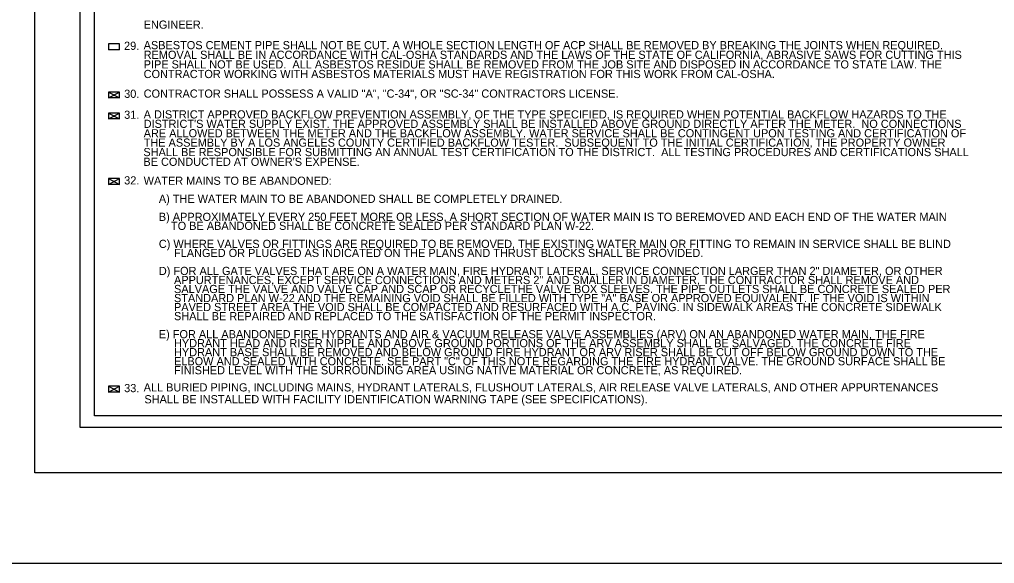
# Model space of a CAD drawing. Extents: x 837 to 1117, y 1316 to 1424.
# Drawn here: x 842.85 to 853.59, y 1398.24 to 1404.23 of the extents above; entities that cross this region are included whole.
import ezdxf

# ---------------------------------------------------------------- set-up
doc = ezdxf.new("R2010")
doc.units = 0
for name, color, linetype in [('0 (Construction)', 7, 'Continuous'), ('BASEMAP', 7, 'Continuous'), ('LLINES', 7, 'Continuous'), ('TEXT', 7, 'Continuous')]:
    doc.layers.add(name, color=color, linetype=linetype)

msp = doc.modelspace()

# ---------------------------------------------------------------- linework, layer by layer
at = {"layer": '0 (Construction)'}
msp.add_lwpolyline([(841.77, 1422.24), (877.77, 1422.24), (877.77, 1398.24), (841.77, 1398.24)], close=True, dxfattribs=at)
at = {"layer": 'BASEMAP'}
for p, q in [((843.02, 1399.24), (843.02, 1421.24)), ((843.52, 1399.74), (843.52, 1420.74)), ((843.678, 1399.867), (843.678, 1420.065)), ((854.857, 1399.867), (843.678, 1399.867)), ((876.52, 1399.74), (843.52, 1399.74)), ((877.02, 1399.24), (843.02, 1399.24))]:
    msp.add_line(p, q, dxfattribs=at)
at = {"layer": 'LLINES'}
for p, q in [((843.95, 1403.965), (843.83, 1403.965)), ((843.83, 1403.965), (843.83, 1403.9)), ((843.95, 1403.9), (843.95, 1403.965)), ((843.95, 1403.9), (843.83, 1403.9)), ((843.831, 1403.435), (843.95, 1403.371)), ((843.831, 1403.371), (843.95, 1403.435)), ((843.95, 1403.435), (843.831, 1403.435)), ((843.95, 1403.371), (843.95, 1403.435)), ((843.95, 1403.371), (843.831, 1403.371)), ((843.95, 1403.204), (843.831, 1403.204)), ((843.831, 1403.14), (843.95, 1403.204)), ((843.831, 1403.204), (843.95, 1403.14)), ((843.95, 1403.14), (843.95, 1403.204)), ((843.95, 1403.14), (843.831, 1403.14)), ((843.951, 1402.481), (843.831, 1402.481)), ((843.831, 1402.417), (843.951, 1402.481)), ((843.831, 1402.481), (843.951, 1402.417)), ((843.951, 1402.417), (843.831, 1402.417)), ((843.951, 1402.417), (843.951, 1402.481)), ((843.951, 1400.193), (843.831, 1400.193)), ((843.831, 1400.128), (843.951, 1400.193)), ((843.831, 1400.193), (843.951, 1400.128)), ((843.951, 1400.128), (843.951, 1400.193)), ((843.951, 1400.128), (843.831, 1400.128))]:
    msp.add_line(p, q, dxfattribs=at)
at = {"layer": 'TEXT'}
for p, q in [((843.831, 1403.435), (843.831, 1403.371)), ((843.831, 1403.204), (843.831, 1403.14)), ((843.831, 1402.481), (843.831, 1402.417)), ((843.831, 1400.193), (843.831, 1400.128))]:
    msp.add_line(p, q, dxfattribs=at)

# ---------------------------------------------------------------- texts
at = {"layer": 'LLINES'}
for s, p in [('ENGINEER.', (844.218, 1404.133)), ('29.', (844.002, 1403.9)), ('ASBESTOS CEMENT PIPE SHALL NOT BE CUT. A WHOLE SECTION LENGTH OF ACP SHALL BE REMOVED BY BREAKING THE JOINTS WHEN REQUIRED.', (844.218, 1403.907)), ('REMOVAL SHALL BE IN ACCORDANCE WITH CAL-OSHA STANDARDS AND THE LAWS OF THE STATE OF CALIFORNIA, ABRASIVE SAWS FOR CUTTING THIS', (844.218, 1403.801)), ('PIPE SHALL NOT BE USED.  ALL ASBESTOS RESIDUE SHALL BE REMOVED FROM THE JOB SITE AND DISPOSED IN ACCORDANCE TO STATE LAW. THE', (844.218, 1403.695)), ('CONTRACTOR WORKING WITH ASBESTOS MATERIALS MUST HAVE REGISTRATION FOR THIS WORK FROM CAL-OSHA.', (844.218, 1403.589)), ('30.', (844.003, 1403.371)), ('CONTRACTOR SHALL POSSESS A VALID "A", "C-34", OR "SC-34" CONTRACTORS LICENSE.', (844.218, 1403.373)), ('31.', (844.003, 1403.14)), ('32.', (844.003, 1402.417)), ('WATER MAINS TO BE ABANDONED:', (844.218, 1402.413)), ('     A) THE WATER MAIN TO BE ABANDONED SHALL BE COMPLETELY DRAINED.', (844.218, 1402.214)), ('     B) APPROXIMATELY EVERY 250 FEET MORE OR LESS, A SHORT SECTION OF WATER MAIN IS TO BEREMOVED AND EACH END OF THE WATER MAIN', (844.218, 1402.015)), ('         TO BE ABANDONED SHALL BE CONCRETE SEALED PER STANDARD PLAN W-22.', (844.218, 1401.916)), ('     C) WHERE VALVES OR FITTINGS ARE REQUIRED TO BE REMOVED, THE EXISTING WATER MAIN OR FITTING TO REMAIN IN SERVICE SHALL BE BLIND', (844.218, 1401.717)), ('          FLANGED OR PLUGGED AS INDICATED ON THE PLANS AND THRUST BLOCKS SHALL BE PROVIDED.', (844.218, 1401.617)), ('     D) FOR ALL GATE VALVES THAT ARE ON A WATER MAIN, FIRE HYDRANT LATERAL, SERVICE CONNECTION LARGER THAN 2" DIAMETER, OR OTHER', (844.218, 1401.419)), ('          APPURTENANCES, EXCEPT SERVICE CONNECTIONS AND METERS 2" AND SMALLER IN DIAMETER, THE CONTRACTOR SHALL REMOVE AND', (844.218, 1401.319)), ('          SALVAGE THE VALVE AND VALVE CAP AND SCAP OR RECYCLETHE VALVE BOX SLEEVES. THE PIPE OUTLETS SHALL BE CONCRETE SEALED PER', (844.218, 1401.22)), ('          STANDARD PLAN W-22 AND THE REMAINING VOID SHALL BE FILLED WITH TYPE "A" BASE OR APPROVED EQUIVALENT. IF THE VOID IS WITHIN', (844.218, 1401.12)), ('          SHALL BE REPAIRED AND REPLACED TO THE SATISFACTION OF THE PERMIT INSPECTOR. ', (844.218, 1400.921)), ('          PAVED STREET AREA THE VOID SHALL BE COMPACTED AND RESURFACED WITH A.C. PAVING. IN SIDEWALK AREAS THE CONCRETE SIDEWALK', (844.218, 1401.021)), ('     E) FOR ALL ABANDONED FIRE HYDRANTS AND AIR & VACUUM RELEASE VALVE ASSEMBLIES (ARV) ON AN ABANDONED WATER MAIN, THE FIRE', (844.218, 1400.722)), ('          HYDRANT HEAD AND RISER NIPPLE AND ABOVE GROUND PORTIONS OF THE ARV ASSEMBLY SHALL BE SALVAGED. THE CONCRETE FIRE', (844.218, 1400.623)), ('          HYDRANT BASE SHALL BE REMOVED AND BELOW GROUND FIRE HYDRANT OR ARV RISER SHALL BE CUT OFF BELOW GROUND DOWN TO THE', (844.218, 1400.524)), ('          ELBOW AND SEALED WITH CONCRETE. SEE PART "C" OF THIS NOTE REGARDING THE FIRE HYDRANT VALVE. THE GROUND SURFACE SHALL BE', (844.218, 1400.424)), ('          FINISHED LEVEL WITH THE SURROUNDING AREA USING NATIVE MATERIAL OR CONCRETE, AS REQUIRED.', (844.218, 1400.325)), ('33.', (844.003, 1400.128)), ('ALL BURIED PIPING, INCLUDING MAINS, HYDRANT LATERALS, FLUSHOUT LATERALS, AIR RELEASE VALVE LATERALS, AND OTHER APPURTENANCES', (844.218, 1400.136)), ('SHALL BE INSTALLED WITH FACILITY IDENTIFICATION WARNING TAPE (SEE SPECIFICATIONS).', (844.226, 1400.005))]:
    msp.add_text(s, height=0.09, dxfattribs=at).set_placement(p)
at = {"layer": 'TEXT'}
for s, p in [('A DISTRICT APPROVED BACKFLOW PREVENTION ASSEMBLY, OF THE TYPE SPECIFIED, IS REQUIRED WHEN POTENTIAL BACKFLOW HAZARDS TO THE', (844.218, 1403.144)), ("DISTRICT'S WATER SUPPLY EXIST. THE APPROVED ASSEMBLY SHALL BE INSTALLED ABOVE GROUND DIRECTLY AFTER THE METER.  NO CONNECTIONS", (844.218, 1403.04)), ('ARE ALLOWED BETWEEN THE METER AND THE BACKFLOW ASSEMBLY. WATER SERVICE SHALL BE CONTINGENT UPON TESTING AND CERTIFICATION OF', (844.218, 1402.936)), ('THE ASSEMBLY BY A LOS ANGELES COUNTY CERTIFIED BACKFLOW TESTER.  SUBSEQUENT TO THE INITIAL CERTIFICATION, THE PROPERTY OWNER', (844.218, 1402.833)), ('SHALL BE RESPONSIBLE FOR SUBMITTING AN ANNUAL TEST CERTIFICATION TO THE DISTRICT.  ALL TESTING PROCEDURES AND CERTIFICATIONS SHALL', (844.215, 1402.729)), ("BE CONDUCTED AT OWNER'S EXPENSE.", (844.215, 1402.622))]:
    msp.add_text(s, height=0.09, dxfattribs=at).set_placement(p)

doc.saveas('drawing.dxf')
